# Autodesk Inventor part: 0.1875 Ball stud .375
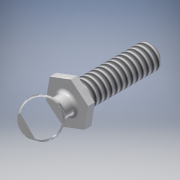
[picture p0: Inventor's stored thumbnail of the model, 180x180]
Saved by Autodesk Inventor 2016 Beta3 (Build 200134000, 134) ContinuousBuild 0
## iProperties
Shininess: 70.0
Length Units: 11272
Angle Units: 11279
Time Units: 11290
Mass Units: 11286
Length Display Precision: 3
Angle Display Precision: 2
Compacted: True
Company: Autodesk
Created: 2000-12
Part Number: 0.1875 Ball stud .375
Document SubType Name: Modeling
Designer: Autodesk, Inc.
Project: Inventor Samples
User Status: IN PROGRESS
Density: 8.08 g/cm^3
Material: Stainless Steel
Mass: 0.939367 g
Surface Area: 1.892 cm^2
Volume: 0.116258 cm^3
Appearance: Steel
Density: 0.0
Volumn: 0.0
Area: 0.0
PropertySet Name: Model Information
Control State: 0
Master: False
Checked Out: False
Author: Autodesk, Inc.
Revision Number: A
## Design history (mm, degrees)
sketch "Sketch3"
  geometry: L1 (-1.183, 7.964)-(-3.755, 6.99); L2 (-3.755, 6.99)-(-4.197, 4.276); L3 (-4.197, 4.276)-(-2.068, 2.536); L4 (-2.068, 2.536)-(0.503, 3.51); L5 (0.503, 3.51)-(0.946, 6.224); L6 (0.946, 6.224)-(-1.183, 7.964); C1 r 2.381 at (-1.626, 5.25)
  constraints: 12 end point, 6 equal length, 6 tangent, 1 centre point, 1 parallel, 1 other
  dimensions: "d2" = 4.7625 diameter of C1
workaxis "Work Axis1"
extrude "Extrusion1" new body sketch "Sketch3" distance "d0" = 0.8128; taper "d1" = 0 deg
sketch "Sketch4"
  geometry: C1 r 1.08 at (-1.626, 5.25); 1 further point
  constraints: 1 centre point, 1 coincident
  dimensions: "d10" = 2.159 diameter of C1
extrude "Extrusion2" join sketch "Sketch4" distance "d11" = 3.175; taper "d12" = 0 deg
sketch "Sketch5"
  geometry: L1 (0, 2.064)-(0, -2.064); C1 r 1.08 at (0, 0) reference; A1 r 2.064 centre (0, 0) between (0, 2.064) and (0, -2.064)
  constraints: 2 end point, 2 point on circle, 1 centre point, 1 coincident, 1 midpoint, 1 vertical
  dimensions: "d13" = 4.1275 diameter of A1
revolve "Revolution1" sketch "Sketch5" stored, may be unused: angle "d14" = 90 deg
fillet "Fillet1" dims "d15" = 0.381
workplane "Work Plane2"
split "Split1"
sketch "Sketch7"
  geometry: C1 r 1.08 at (1.626, 5.25) reference; C2 r 1.422 at (1.626, 5.25)
  constraints: 1 centre point, 1 coincident
  dimensions: "d21" = 2.8448 diameter of C2
extrude "Extrusion3" join sketch "Sketch7" distance "d22" = 9.525; taper "d23" = 0 deg
chamfer "Chamfer1" distance "d24" = 0.381; stored, may be unused: second distance "d25" = 0.381, angle "d28" = 45 deg
thread "Thread1" dims "d26" = 25.4, "d27" = 0
body "Solid1"
other parameters: "d16" = 4.7625
